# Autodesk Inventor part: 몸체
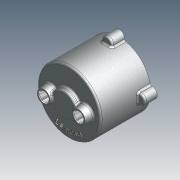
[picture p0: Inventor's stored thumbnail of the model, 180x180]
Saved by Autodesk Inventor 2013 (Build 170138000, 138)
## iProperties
Company: 한국ATC센터
Created: 2012-05
Part Number: 몸체
Document SubType Name: 모델링
Designer: KYOUNG IL JANG
Mass: 471.042 g
Surface Area: 679.306 cm^2
Volume: 173.816 cm^3
Density: 2.71 g/cm^3
Material: 알루미늄-6061
변환 표준: STEP AP214IS
파일 이름: C:\Users\SeoGD\Desktop\?쒗뿕\紐몄껜.stp
전처리기: Build: 253, Release: 2010 SP1 - Date: Wed 07/29/2009
전송 단위: 밀리미터
불확실성: 0.01
Author: KYOUNG IL JANG
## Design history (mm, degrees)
sketch "스케치2"
  geometry: C1 r 50 at (0, 0); 1 further point
  constraints: 1 centre point, 1 coincident
  dimensions: "d9" = 100 diameter of C1
extrude "돌출2" new body sketch "스케치2" distance "d10" = 80; taper "d11" = 0 deg
feature "쉘1" dims "d12" = 5
sketch "스케치3" dims "d13" = 55
  geometry: C1 r 7.5 at (27.5, 0); C2 r 12.5 at (27.5, 0); 2 further points
  constraints: 2 centre point, 2 coincident, 2 horizontal alignment, 2 other
  dimensions: "d14" = 15 diameter of C1; "d15" = 25 diameter of C2
extrude "돌출3" join sketch "스케치3" distance "d16" = 12; taper "d17" = -10 deg
hole "구멍2" diameter "d20" = 15; stored, may be unused: countersink angle "d24" = 90 deg, drill point angle "d26" = 118 deg; dims "d18" = 10, "d19" = 10, "d21" = 6, "d22" = 4, "d23" = 2, "d25" = 15
chamfer "모따기1" distance "d27" = 1; stored, may be unused: second distance "d28" = 2, angle "d29" = 45 deg
sketch "스케치4"
  geometry: L1 (0, 0)-(0, 88); L2 (0, 70)-(13.16, 70); L3 (-45, 75)-(45, 75) reference; L4 (-50, 80)-(50, 80) reference; L5 (13.16, 70)-(14.5, 75); L6 (20, 80)-(20, 88); L7 (20, 88)-(0, 88); L8 (20, 80)-(14.5, 75)
  constraints: 12 end point, 3 point on line, 2 perpendicular, 1 vertical
  dimensions: "d34" = 40 diameter of L6 L1; "d35" = 105 deg angle of L5 L3; "d36" = 5 distance between parallel lines of L2 L3; "d37" = 8 distance between parallel lines of L7 L4; "d51" = 29 diameter of L5.end L1
revolve "회전1" sketch "스케치4" stored, may be unused: angle "d38" = 90 deg
hole "구멍3" diameter "d41" = 15; stored, may be unused: countersink angle "d45" = 90 deg, drill point angle "d47" = 0 deg; dims "d39" = 10, "d40" = 10, "d42" = 6, "d43" = 22, "d44" = 13, "d46" = 15
chamfer "모따기2" distance "d48" = 1; stored, may be unused: second distance "d49" = 2, angle "d50" = 45 deg
fillet "모깎기1" dims "d52" = 3
fillet "모깎기2" dims "d53" = 3, "d72" = 0.2
sketch "스케치5"
  geometry: A1 r 50 centre (0, 0) between (50, 0) and (-8.074, 49.344) reference; A2 r 8.5 centre (0, 52) between (8.074, 49.344) and (-8.074, 49.344); 1 further point
  constraints: 5 point on circle, 1 centre point, 1 horizontal alignment
  dimensions: "d54" = 90 deg dimension on point (0, 0) A2.centre A1.start; "d55" = 52 distance of A2.centre point (0, 0); "d56" = 17 diameter of A2
extrude "돌출4" join sketch "스케치5" distance "d57" = 20; taper "d58" = 0 deg
fillet "모깎기3" dims "d59" = 3
hole "구멍4" diameter "d62" = 4.134; stored, may be unused: countersink angle "d66" = 90 deg, drill point angle "d68" = 118 deg; dims "d60" = 10, "d61" = 10, "d63" = 12, "d64" = 22, "d65" = 13, "d67" = 15
sketch "스케치6"
  geometry: C1 r 47 at (0, 0) reference; C2 r 42.5 at (0, 0); 1 further point
  constraints: 1 centre point, 1 coincident, 1 other
  dimensions: "d73" = 85 diameter of C2
feature "엠보싱1" sketch "스케치6" dims "d74" = 1, "d75" = 0
node "솔리드1"
node "솔리드 본체"
node "곡면 본체"
pattern_circular "원형 패턴1" dims "d31" = 360 deg
pattern_circular "원형 패턴2" dims "d70" = 360 deg
node "솔리드2"
